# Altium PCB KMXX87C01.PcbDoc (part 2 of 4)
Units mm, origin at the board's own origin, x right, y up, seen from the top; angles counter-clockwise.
Board outline 109.2 x 85.1 mm, 4 copper layers (Top Layer, Mid-Layer 1, Mid-Layer 2, Bottom Layer); 294 components, 222 nets, 951 pads, 352 vias.
Unrouted connection lines stored in the file: 266.
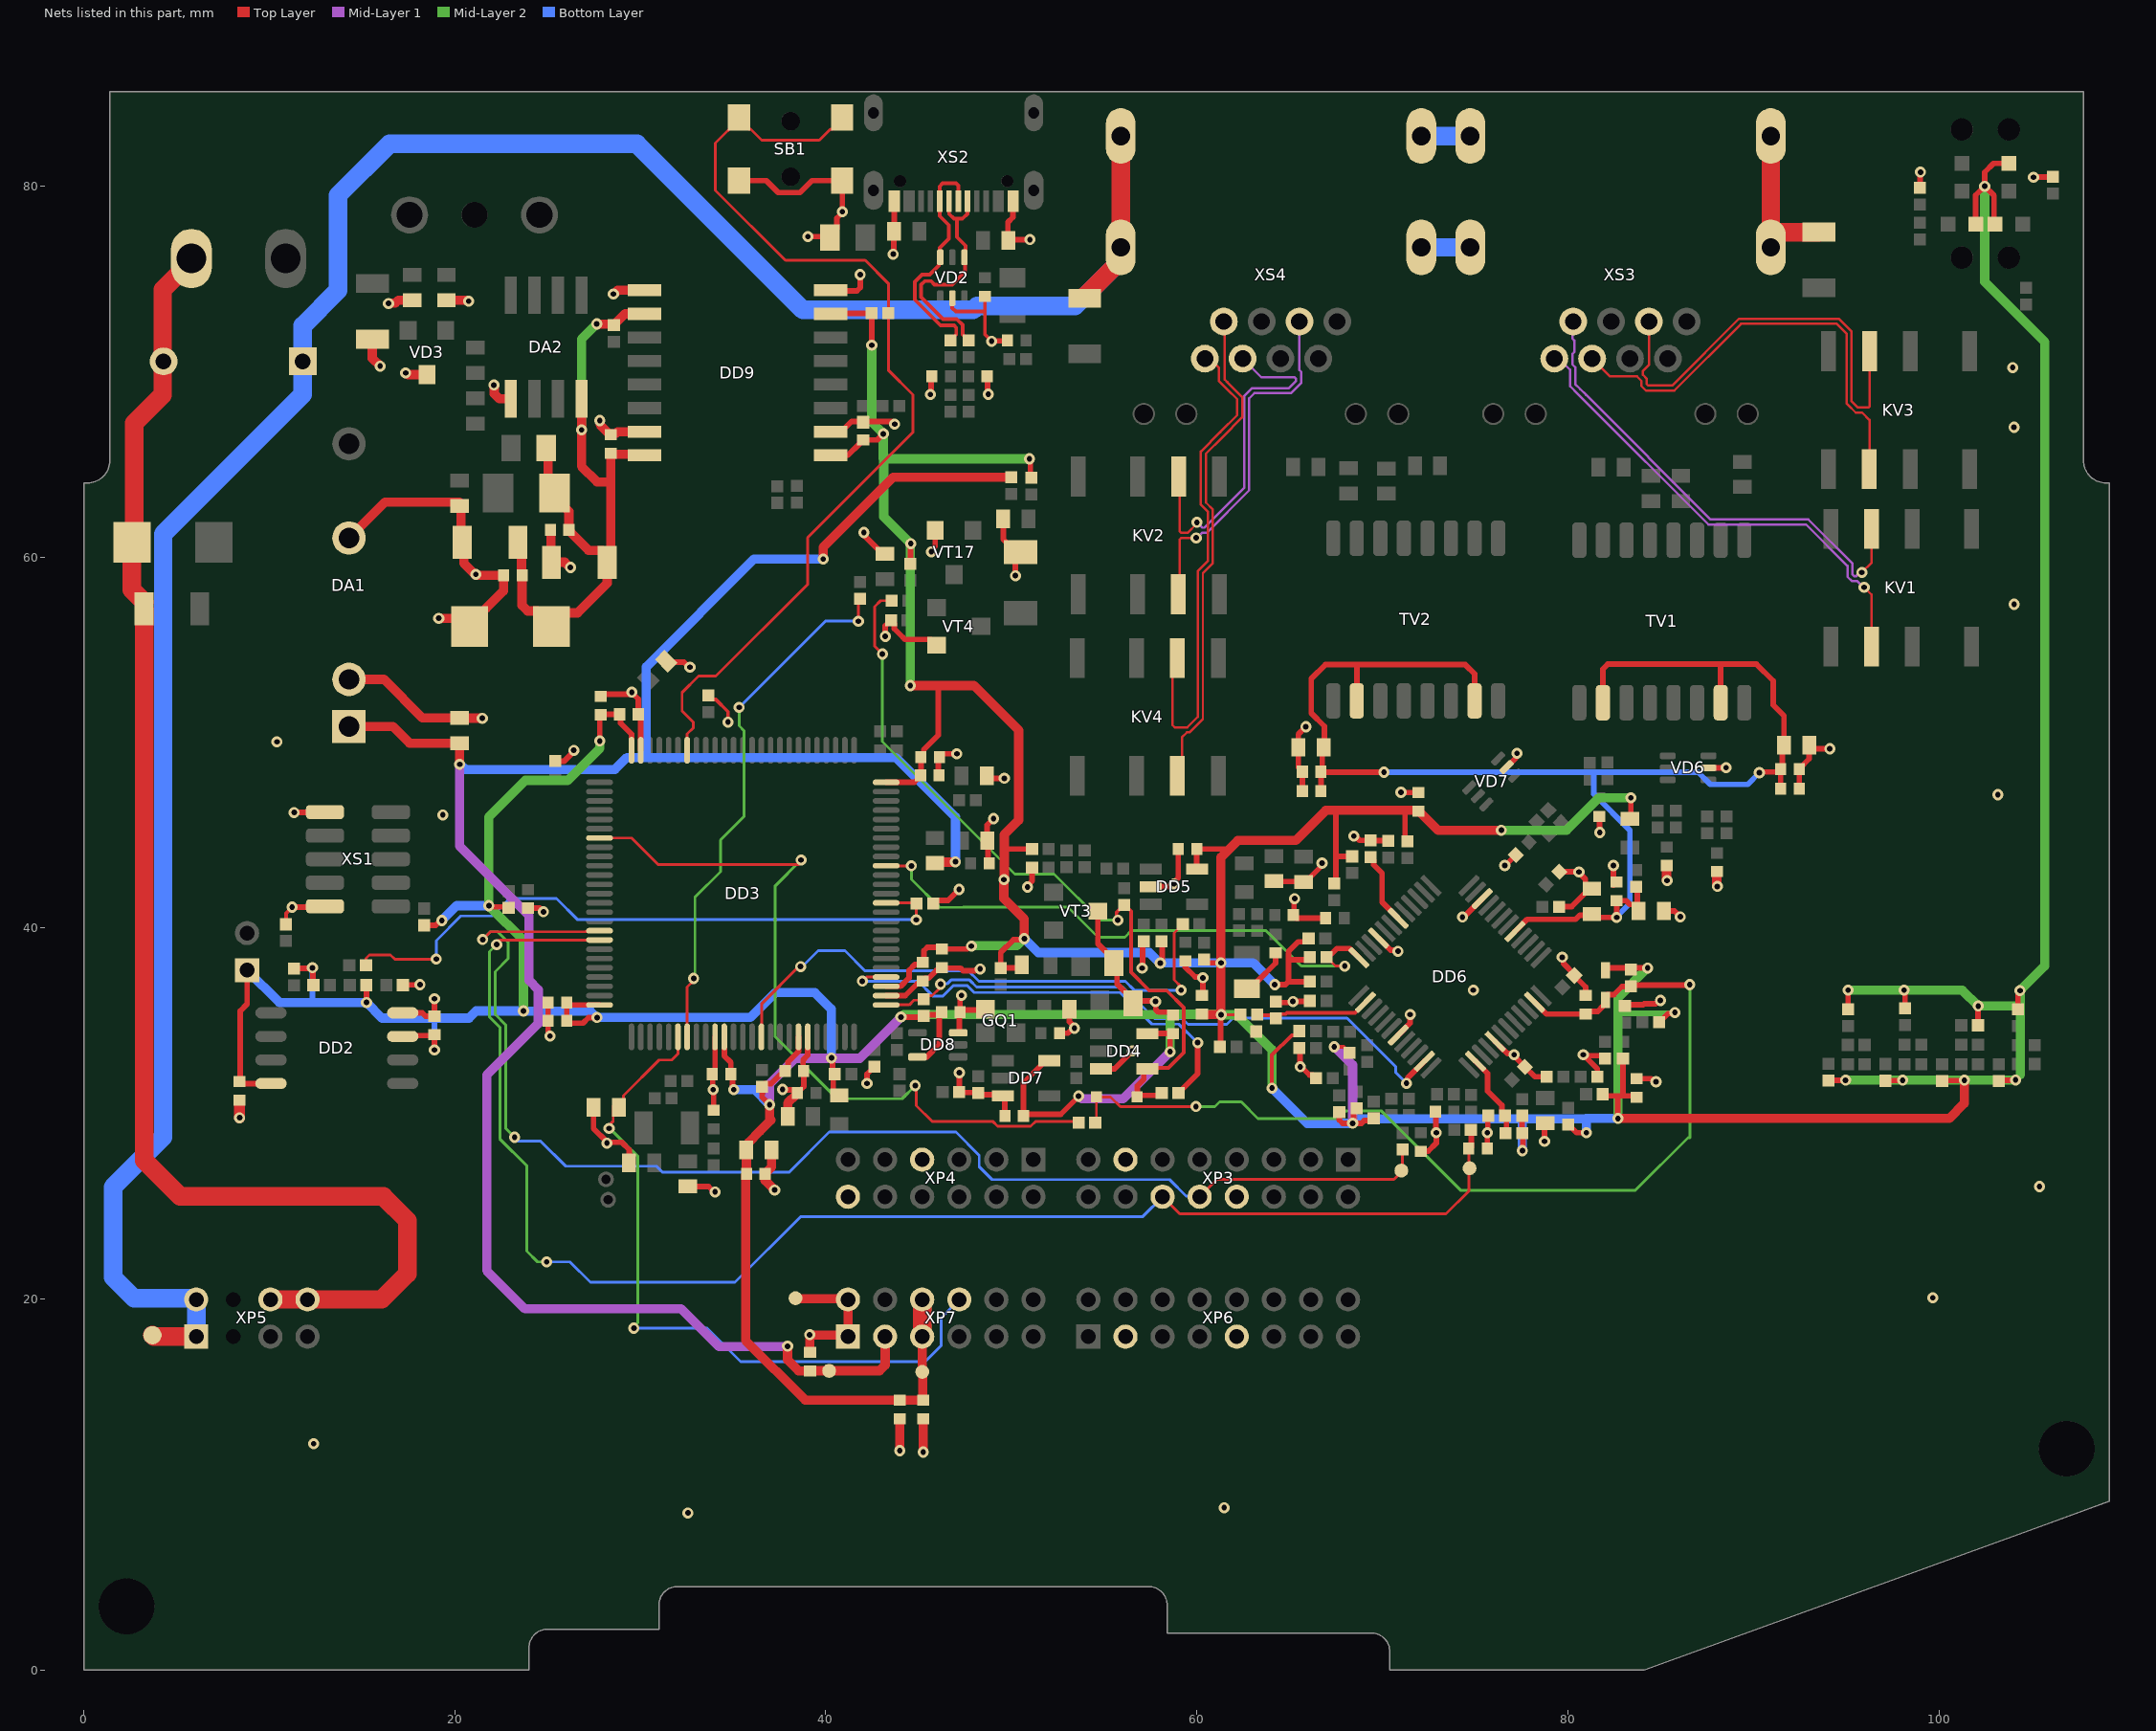
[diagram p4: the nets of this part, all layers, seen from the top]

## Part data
BQ1: library part NX3215SA, "NX3215SA"
BQ2: library part MMTF32, "MMTF32"
C2: library part JY-8, "JY-8"
C3 C4 C5 C6 C10 C12 C13 C14 C15 C16 C18 C19 C21 C24 C25 C26 C28 C29 C30 C31 C32 C33 C34 C35 C36 C37 C39 C40 C42 C44 C45 C47 C48 C50 C51 C53 C54 C55 C56 C57 C58 C59 C60 C72 C73 C74 C75 C76 C120 C122 C124 C125 C126 C144 C145: library part C0402, "C0402"
C7 C8 C9 C11 C17 C20 C22 C23 C27 C43 C46 C61 C102 C146 C169 C170 C171 C172 C173: library part C0603, "C0603"
C38 C49 C62 C63 C67: library part C1206, "C1206"
C41 C52 C150: library part C0805, "C0805"
C64 C65: library part C0603, "C0603", Value2=C0603-50В-100пФ-5%-NPO
DA1: library part F0505S-1W, "F0505S-1W"
DA2: library part ADM485AR, "ADM485AR"
DD2: library part MX25L6433FM2I-08G, "EEPROM Flash Memory, NOR, Serial SPI/QSPI Interface, f=80/133MHz, 64-Mbit, Vcc=2.7V...3.6V, SOIC-8 (200mil). SMT", Value2=MX25L3233FM2I-08G
DD3: library part STM32F207VCT6, "ARM-based 32-bit MCU with 256KB Flash"
DD4: library part SN74LVC1G17DBV, "SN74LVC1G17DBV"
DD5: library part XC6121-24, "Voltage Detector with Watchdog Function and ON/OFF Control"
DD6: library part KSZ8863RLLI, "Integrated 3-Port 10/100 Managed Switch with PHYs"
DD7: library part SN74LVC1G80DBV, "Single Positiive Edge Triggered D-Type Flip-Flop"
DD8: library part SN74LVC1G125DCK, "Buffer / line driver"
DD9: library part ADUM1301, "ADUM1301"
GQ1: library part FXO2520, "SMD Crystal Oscillator 2.5x2.0, 2.0-50.0 MHz, 3.3V", Value2=DSO221SHF, Value3=NZ2520SB
HL1 HL2 HL15 HL16: library part HT19-2132SYGC, "High Brigh Yellow-Green LED"
KV1 KV2 KV3 KV4: library part "Hongfa HFD4/5-S (standard SMT)", "High Frequency / RF Relays 5VDC Non-latching Single coil gullwing", Value2="TE IM03GR Gul wings"
L1 L2 L3 L11: library part L0603, "L0603"
L4 L5 L8: library part L0805, "L0805"
L6: library part L1206, "Inductor, 1206, 1uH, 1200mA, 0.15Ohm", Value2="L1206-1,0мкГн-20% (MURATA, LQM31)"
R1 R9 R14 R16 R18 R23 R25 R26 R40 R98 R99 R100 R101 R106 R107 R325 R329: library part RC03, "RC03"
R2 R3 R4 R5 R6 R7 R8 R10 R11 R12 R15 R17 R19 R20 R21 R22 R24 R27 R28 R29 R30 R31 R32 R33 R34 R35 R36 R37 R38 R39 R41 R42 R43 R44 R45 R46 R47 R49 R50 R51 R52 R53 R54 R55 R56 R57 R58 R59 R60 R61 R62 R63 R64 R65 R66 R67 R68 R69 R70 R71 R72 R73 R74 R75 R76 R77 R78 R79 R80 R81 R82 R83 R84 R85 R86 R87 R88 R89 R90 R91 R92 R93 R94 R95 R96 R97 R102 R103 R104 R105 R108 R109 R110 R111 R112 R113 R114 R115 R169 R200 R201 R202 R233 R234 R268 R269 R270 R271 R318 R319 R320 R321 R322 R326 R327 R357 R358 R378 R380 R381 R383 R400: library part R0402, "R0402"
R48: library part R0402, "R0402", Value2="RC02-1,0кОм 5%"
R116: library part RC06, "Chip Resistor, 1206, Pmax=0.25W, Umax=200V, SIZE=3.2x1.6x0.6mm, SMT"
R167: library part RC03, "RC03", Value2="RC02-0,0 Ом 5%"
R317 R328: library part R0402, "R0402", Value2="RC02-0,0 Ом 5%"
SB1: library part TP-1113, "TP-1113"
T1: library part T17A, "T17A"
T2 T3 T4 T5 T6: library part T07A, "T07A"
TV1 TV2: library part PT61018PEL_TRC1188NLE, "Pulse Transformer 1CT_1CT Lan 10/100 Base TX Transormer Module"
VD1: library part SMBJ6.5, "SM6T27A"
VD2 VD6 VD7: library part TPD4E001DCKR, "4-Channel ESD Protection Array with 1.5pF IO Cap."
VD3: library part SM712, "600W, Asymmetrical TVS Diode Array"
VD4: library part BAS16WS, "BAS16WS", Value2="BAS16HT1G (ON, SOD-323)"
VD5: library part P6KE7,5, "P6KE7,5"
VD8: library part BZV55C, "BZV55C"
VD20: library part BAS716, "Low-Leakage Diode"
VT3: library part BC807-25, "BC807-25"
VT4 VT17: library part BC817-25, "BC817-25"
XP1: library part 2EDGR-5.08-02P, "2EDGR-5.08-02P"
XP2: library part JUMP1X2_2MM, "JUMP1X2_2MM"
XP3 XP6: library part PLD2-16, "PLD2-16", Value2="DS1025-05-2*8 (Connfly)"
XP4 XP7: library part PLD2-12_MULTI, "Pin Header, Straight, Male, POS=12, ROW=2, PITCH=2.0mm, H=6.0mm, I=1.5A, U=125VAC, THT", Value2="DS1025-08-2*6 (Connfly)"
XP5: library part PLD2-08, "Pin Header, Straight, Male, POS=8, ROW=2, PITCH=2.0mm, H=6.0mm, I=1.5A, U=125VAC, THT", Value2="DS1025-05-2*4 (Connfly)"
XS1: library part PBD1.27-10S, "PBD1.27-10S"
XS2: library part USB4105-GF-A-xxx, "USB-C (USB TYPE-C) USB 2.0 Receptacle Connector 24 (16+8 Dummy) Position Surface Mount, Right Angle; Through Hole"
XS3 XS4: library part MJ881B-BX11-HRVL11-X, "RJ45 Offset Low Profile Connector, Latch - Tab UP, Magnetic - none"
XT2: library part 15EDGRC-3.5-03P_MULTI, "Right angle, 3.5 mm pitch, 3 pins", Value2="(1803316) MC 1,5/ 6-G-3,81 - PCB header (Phoenix Contact)"

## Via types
v1: diameter 0.6, hole 0.3, Top Layer to Bottom Layer, tented both sides, 292 vias
v2: diameter 0.6, hole 0.3, Top Layer to Bottom Layer, 60 vias

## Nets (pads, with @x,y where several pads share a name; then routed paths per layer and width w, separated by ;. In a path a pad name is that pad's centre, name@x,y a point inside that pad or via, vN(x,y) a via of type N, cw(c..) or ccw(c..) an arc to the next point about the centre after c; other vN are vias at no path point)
3.3V: C3.1 C5.2 C12.1 C13.1 C14.1 C15.1 C16.1 C18.1 C21.1 C23.1 C24.1 C25.1 C26.1 C28.1 C29.1 C30.1 C32.1 C34.1 C35.1 C37.1 C40.1 C42.1 C144.1 C145.1 DD2.3 DD2.8 DD3.11 DD3.19 DD3.28 DD3.50 DD3.75 DD3.100 DD4.5 DD5.5 DD7.5 DD8.5 DD9.1 DD9.7 HL1.A HL15.A HL16.A L1.2 L3.2 L11.1 R2.2 R11.2 R12.2 R19.2 R21.2 R22.2 R28.1 R29.2 R36.2 R39.2 R41.2 R42.1 R47.1 R49.2 R50.2 R51.2 R54.2 R57.1 R58.1 R60.2 R62.2 R66.1 R67.1 R70.1 R71.2 R80.1 R81.1 R82.1 R83.1 R84.1 R86.1 R103.1 R104.1 R108.1 R110.1 R112.1 R114.1 R167.2 R318.2 R319.2 R320.2 R321.2 R322.2 R326.2 T4.1 VD20.2 XP2.1 XP7.5 XP7.6 | length 494.5
  Top Layer w0.15: v1@61.295,35.344 v1(61.31,35.329) 62.34,35.329 R57.1@62.35,35.338
  Top Layer w0.2: v1(64.05,31.375) 64.05,33.157 65.118,34.225 65.346,34.225 R60.2@65.525,34.404 ; v1(67.404,33.6) 67.913,33.6 R62.2@68.237,33.277
  Top Layer w0.3: C16.1@8.334,31.609 10.08,31.609 DD2.8@10.09,31.619 ; C16.1@8.391,31.716 C16.1@8.4,31.725 8.425,31.75 8.425,35.525 8.8,35.9 XP2.1@8.8,37.729 ; R22.2@11.325,37.807 11.35,37.832 12.3,37.832 v1(12.325,37.857) 12.35,37.832 12.35,36.95 R21.2@12.375,36.925 ; v1(15.236,35.989) R326.2@15.236,36.925 ; DD2.3@17.19,34.159 17.235,34.204 18.854,34.204 C32.1@18.9,34.25 v1(18.9,33.431) ; R19.2@17.2,36.925 17.214,36.939 18.108,36.939 v1(18.123,36.954) ; R2.2@18.35,40.15 18.961,40.15 19.219,40.407 v1(19.3,40.407) ; v1(21.836,41.203) 21.9,41.14 22.698,41.14 R39.2@22.748,41.09 ; C35.1@26.031,35.989 C15.1@26.031,35.001 26.157,34.875 26.911,34.875 27.213,35.177 v1(27.664,35.177) ; C35.1@26.324,35.857 DD3.100@27.8,35.857 ; v1(27.814,50.085) 27.814,51.464 27.875,51.525 C25.1@28.887,51.525 28.932,51.48 28.932,51.05 29.525,50.457 DD3.75@29.525,49.582 ; DD3.11@34.525,34.093 34.525,33.11 34.88,32.754 C34.1@34.88,32.128 ; C34.1@34.884,32.128 34.964,32.049 34.964,31.357 v1(35.032,31.289) ; v1@36.965,30.474 36.565,30.874 R12.2@36.565,31.44 36.74,31.615 37.046,31.615 37.546,32.115 37.661,32.115 37.811,32.265 C28.1@37.811,32.29 ; C28.1@37.961,32.415 37.961,32.786 38.525,33.35 DD3.19@38.525,34.132 ; DD9.1@40.267,65.493 41.19,65.493 41.84,66.142 41.84,66.167 41.99,66.317 42.771,66.317 v1(43.1,66.646) ; DD9.7@40.267,73.113 40.289,73.136 42.447,73.136 R36.2@42.47,73.158 42.472,73.156 42.472,71.428 v1(42.475,71.425) ; v1(40.303,33) 40.368,32.935 40.368,32.232 40.4,32.2 40.4,31.191 L1.2@40.616,30.975 ; DD3.28@43.25,36.857 44.032,36.857 44.494,37.319 44.494,37.724 44.811,38.041 C30.1@45.135,38.041 ; DD3.50@43.25,47.857 44.777,47.857 C37.1@44.985,48.066 ; v1(44.052,35.202) R29.2@45.185,35.202 ; R322.2@44.551,59.645 44.563,59.657 44.563,60.713 v1(44.575,60.725) ; DD8.5@44.938,33.054 44.947,33.063 45.453,33.063 46.12,33.73 46.12,35.288 46.083,35.324 R29.2@45.185,35.324 ; C37.1@45.11,48.244 45.138,48.271 45.138,49.212 C21.1@45.125,49.225 45.275,49.375 45.275,49.613 46.067,50.405 46.067,53.075 ; C30.1@45.225,38.05 45.288,38.113 45.288,38.781 45.463,38.956 46.144,38.956 C14.1@46.162,38.937 ; C14.1@46.25,38.875 47.619,38.875 47.769,39.025 v1(47.85,39.025) ; 49.625,44.357 49.72,44.262 R47.1@51.118,44.262 ; L11.1@50.57,38.018 50.402,37.85 R167.2@49.425,37.85 49.425,38.686 50.107,39.368 50.643,39.368 v1(50.7,39.425) ; v1(50.975,65.3) 51.024,65.251 51.024,64.329 R103.1@51.072,64.281 ; DD7.5@52.134,32.84 51.834,32.84 50.654,31.66 C144.1@50.654,29.862 50.75,29.958 52.666,29.958 53.625,30.917 v2(53.625,30.94) ; DD4.5@57.335,34.313 C40.1@58.56,34.313 ; v1(58.029,38.109) 58.137,38.218 58.137,39.237 R41.2@58.1,39.275 ; v1(58.56,33.336) C40.1@58.56,34.313 ; C40.1@58.712,34.313 C40.1@58.56,34.313 ; C42.1@59.991,44.115 59.991,43.207 DD5.5@60.016,43.182 ; C42.1@60,44.241 C42.1@60,44.266 61.575,44.266 61.657,44.185 ; R28.1@60.4,38.3 60.575,38.125 60.751,38.125 v1@61.295,38.125 ; R58.1@61.25,33.6 61.28,33.63 61.28,35.329 v1@61.295,35.344 ; v1(64.202,36.95) 64.774,36.95 64.935,37.112 ; R70.1@66.029,39.436 65.854,39.261 65.461,39.261 64.935,38.735 64.935,38.3 ; R54.2@66.096,37.112 64.935,37.112 ; R49.2@66.1,38.425 65.975,38.3 64.935,38.3 ; R318.2@67.415,42.405 67.493,42.483 67.493,43.866 ; 67.493,46.35 67.493,43.866 ; R51.2@67.679,30.071 67.679,29.651 67.855,29.475 v1(68.4,29.475) ; R319.2@68.372,43.866 67.493,43.866 ; R50.2@68.537,30.202 68.457,30.122 68.457,29.532 v1(68.4,29.475) ; R321.2@69.537,29.75 69.412,29.625 69.025,29.625 68.875,29.475 v1(68.4,29.475) ; 71.22,46.35 71.22,44.826 71.21,44.817 R320.2@71.356,44.671 ; R67.1@77.537,29.882 R80.1@77.537,28.932 77.576,28.893 77.576,28.027 v1(77.55,28.001) ; R84.1@80.025,29.407 80.467,28.965 v1(81,28.965) ; R81.1@81.885,31.046 81.975,30.956 82.681,30.956 ; VD20.2@82.029,37.725 82.029,37.75 82.129,37.85 v1(84.3,37.85) ; v1(82.704,29.735) 82.681,29.758 82.681,30.956 ; R83.1@82.975,32.975 82.975,30.981 83,30.956 ; L3.2@83.35,45.9 83.4,45.95 v1(83.4,47.024) ; C29.1@83.7,30.885 83.629,30.956 83,30.956 ; R82.1@84.925,34.925 85.393,35.393 85.718,35.393 v1(85.775,35.45) ; R112.1@94.05,31.773 94.064,31.786 94.961,31.786 v1(94.975,31.8) ; R114.1@95.1,35.623 95.109,35.632 v1(95.109,36.653) ; R110.1@97.125,31.767 97.141,31.784 98.034,31.784 v1(98.05,31.8) ; v1(98.126,36.65) 98.175,36.601 R108.1@98.175,35.666 ; R104.1@100.175,31.75 100.2,31.775 101.35,31.775 v1(101.375,31.8) ; HL16.A@101.989,77.956 101.989,79.506 v1(102.475,79.992) ; R86.1@102.112,34.761 102.118,34.767 102.118,35.791 v1(102.125,35.798) ; HL15.A@103.029,77.956 102.975,78.01 102.975,79.492 v1(102.475,79.992) ; R66.1@103.225,31.759 103.252,31.785 104.106,31.785 v1(104.133,31.812) ; HL1.A@103.779,81.226 102.954,81.226 102.475,80.747 v1(102.475,79.992) ; R42.1@104.268,35.619 v1@104.268,36.44 ; 64.935,37.112 64.935,38.3 ; 82.681,30.956 83,30.956
  Top Layer w0.5: v1(36.968,30.478) 36.965,30.474 36.965,29.725 37.04,29.65 36.439,29.05 35.84,28.451 35.84,28.167 C23.1@35.715,28.042 35.715,26.765 35.675,26.725 35.675,17.768 38.893,14.55 C12.1@43.995,14.55 C3.1@45.25,14.55 45.225,14.575 45.225,16.05 T4.1@45.2,16.075 45.198,16.077 45.198,17.974 XP7.5@45.195,17.976 ; v1(44.551,53.075) 46.067,53.075 47.987,53.075 50.4,50.662 50.4,45.814 49.625,45.039 49.625,44.357 v1@49.625,42.612 ; v1(49.6,42.612) 49.6,41.59 50.7,40.49 v1(50.7,39.425) ; C24.1@60.275,35.363 60.292,35.346 61.293,35.346 61.295,35.344 61.295,38.125 61.295,43.823 61.657,44.185 62.199,44.727 65.329,44.727 66.952,46.35 67.493,46.35 71.22,46.35 71.898,46.35 C26.1@71.948,46.3 71.973,46.3 72.998,45.275 v1(76.414,45.275) ; v1(82.704,29.735) 100.567,29.735 101.375,30.543 v1(101.375,31.8)
  Top Layer w1: XP7.5@45.195,17.976 XP7.6@45.195,19.976
  Mid-Layer 1 w0.5: v1(36.968,30.478) 36.965,30.482 36.965,31.59 38.357,32.982 40.285,32.982 v1(40.303,33) ; v1@40.31,32.982 41.833,32.982 v1(44.052,35.202) ; v2(53.625,30.94) 53.652,30.94 53.795,30.797 56.021,30.797 v1(58.56,33.336) ; v1(67.404,33.6) 67.425,33.6 68.4,32.626 v1(68.4,29.475)
  Mid-Layer 2 w0.3: 82.704,35.408 85.733,35.408 v1(85.775,35.45)
  Mid-Layer 2 w0.5: v1(21.836,41.203) 21.836,45.998 23.805,47.967 26.093,47.967 27.814,49.689 v1(27.814,50.085) ; v1@21.9,41.14 23.698,39.341 v1(23.698,35.532) ; v1(42.475,71.425) 42.475,67.295 43.1,66.671 43.1,65.325 43.125,65.3 ; v1(44.052,35.202) 44.193,35.342 58.609,35.342 58.619,35.352 ; v1(44.551,53.075) 44.551,60.701 v1(44.575,60.725) 43.125,62.175 43.125,65.3 ; v1(47.85,39.025) 47.875,39.05 50.298,39.05 50.673,39.425 v1(50.7,39.425) ; v1(50.975,65.3) 43.125,65.3 ; v1(58.56,33.336) 58.56,35.293 58.619,35.352 ; v1@61.183,35.352 58.619,35.352 ; v1(61.31,35.329) 62.161,35.329 64.05,33.44 v1(64.05,31.375) ; v1(76.414,45.275) 79.938,45.275 81.687,47.024 v1(83.4,47.024) ; v1(82.704,29.735) 82.704,35.408 82.704,36.254 v1(84.3,37.85) ; v1(94.975,31.8) v1(98.05,31.8) v1(101.375,31.8) 101.387,31.812 v1@104.134,31.812 ; v1(95.109,36.653) 95.112,36.65 v1(98.126,36.65) 101.273,36.65 v1(102.125,35.798) 104.319,35.798 104.396,35.875 ; v1(102.475,79.992) 102.475,74.839 105.704,71.61 105.704,37.957 v1(104.377,36.63) ; 104.396,32.102 104.396,35.875 ; v1@104.41,36.598 104.396,36.584 104.396,35.875
  Mid-Layer 2 w1: XP7.5@45.195,17.976 XP7.6@45.195,19.976
  Bottom Layer w0.3: v1(12.325,37.857) 12.325,36.055 12.391,35.989 ; v1(18.9,33.431) 18.9,35 19.05,35.15
  Bottom Layer w0.5: XP2.1@8.8,37.729 10.54,35.989 12.391,35.989 v1(15.236,35.989) 16.075,35.15 19.05,35.15 20.769,35.15 21.15,35.532 v1(23.698,35.532) 23.716,35.514 27.307,35.514 27.644,35.177 35.927,35.177 37.275,36.525 39.408,36.525 40.294,35.639 40.294,33.009 v1(40.303,33) ; v1(19.3,40.407) 20.096,41.203 v1(21.836,41.203) ; v1(35.032,31.289) 36.157,31.289 v1(36.968,30.478) ; v1(50.7,39.425) 51.45,38.675 57.436,38.675 58.002,38.109 v1(58.029,38.109) 58.037,38.117 61.292,38.117 v1(61.3,38.125) 63.027,38.125 v1(64.202,36.95) ; v1(64.05,31.375) 65.95,29.475 v1(68.4,29.475) 68.64,29.715 77.565,29.715 ; v1(77.55,28.001) 77.55,29.7 77.565,29.715 ; v1(81,28.965) 81,29.69 80.975,29.715 80.965,29.715 ; v1(82.704,29.735) 80.985,29.735 80.965,29.715 ; 77.565,29.715 80.965,29.715
3.3VDDA: C43.1 C44.1 C57.1 C58.1 C59.1 C60.1 C169.1 C172.1 C173.1 DD6.5 R72.1 TV1.2 TV1.7 TV2.2 TV2.7 | length 82.8
  Top Layer w0.3: C58.1@66.69,47.38 C60.1@66.69,48.43 ; C173.1@66.833,49.747 66.762,49.676 66.762,48.502 C60.1@66.69,48.43 ; C173.1@66.875,49.776 66.875,50.882 66.168,51.589 66.168,53.443 66.925,54.2 68.625,54.2 ; TV2.2@68.624,52.25 68.624,54.199 68.625,54.2 ; v1(70.089,48.404) 66.717,48.404 C60.1@66.69,48.43 ; TV2.7@74.974,52.25 74.974,53.701 74.475,54.2 68.625,54.2 ; DD6.5@77.15,39.818 77.807,40.475 80.425,40.475 80.643,40.693 81.233,40.693 C43.1@81.296,40.756 81.479,40.574 v1(82.631,40.574) 82.631,41.331 C44.1@82.658,41.357 ; TV1.2@81.89,52.15 81.89,53.965 82.15,54.225 88.15,54.225 ; C44.1@82.615,41.481 83.144,41.481 83.349,41.275 83.595,41.275 83.82,41.05 C169.1@83.82,40.925 83.747,40.997 83.747,41.098 83.747,42.153 R72.1@83.675,42.225 ; TV1.7@88.24,52.15 88.24,54.135 88.15,54.225 ; v1@90.297,48.266 90.45,48.419 91.328,48.419 C59.1@91.473,48.564 ; C57.1@91.478,47.514 91.476,47.517 91.476,48.562 C59.1@91.473,48.564 ; 88.15,54.225 90.175,54.225 91.075,53.325 91.075,52.025 91.648,51.452 C172.1@91.648,49.864 91.561,49.777 91.561,48.652 C59.1@91.473,48.564
  Bottom Layer w0.3: v1(70.089,48.404) 81.4,48.404 ; v1(82.631,40.574) 82.631,40.614 83.35,41.333 83.35,45.275 81.4,47.225 81.4,48.404 ; v1(90.325,48.375) 89.7,47.75 87.675,47.75 87.021,48.404 81.4,48.404
5V: C4.2 C9.1 DA1.1 R14.1 R102.1 T3.1 XP7.3 | length 124.7
  Top Layer w0.5: DA1.1@14.291,50.867 16.662,50.867 17.559,49.97 C9.1@20.262,49.97 ; v1@20.263,48.826 C9.1@20.262,49.97 ; v1(37.937,17.458) 37.937,16.721 38.533,16.125 C4.2@39.15,16.125 39.157,16.132 T3.1@40.18,16.132 40.188,16.14 42.902,16.14 43.195,16.433 XP7.3@43.195,17.976 ; v1@39.857,59.876 v1(39.857,59.897) 39.857,60.539 43.618,64.3 R102.1@50,64.3 ; R14.1@45.882,43.502 45.936,43.556 46.967,43.556 v1(46.986,43.575)
  Mid-Layer 1 w0.5: v1(20.263,48.826) 20.263,44.412 24,40.675 24,37.175 24.5,36.675 24.5,34.85 21.725,32.075 21.725,21.537 23.787,19.475 32.201,19.475 34.239,17.437 v1@37.937,17.437
  Bottom Layer w0.5: v1(20.263,48.826) 20.29,48.826 20.566,48.55 28.628,48.55 29.276,49.197 43.779,49.197 46.986,45.991 v1(46.986,43.575) ; 30.322,49.197 30.322,54.082 36.136,59.897 v1(39.857,59.897)
5V_RS: C10.2 C31.2 C38.2 C39.2 C49.2 DA2.8 DD9.10 DD9.16 L5.2 L6.2 R17.2 VD1.2 | length 39.5
  Top Layer w0.5: C49.2@23.282,60.792 23.6,60.474 23.6,59.043 C39.2@23.627,59.017 23.627,57.393 23.92,57.1 24.458,57.1 VD1.2@25.208,56.35 ; L5.2@25.025,66.014 25.025,63.583 26.15,62.458 C31.2@26.15,61.45 ; VD1.2@25.208,56.45 25.755,56.997 26.622,56.997 28.215,58.59 C38.2@28.215,59.031 ; C31.2@26.15,61.475 26.2,61.425 26.2,61.375 27.211,60.364 C38.2@27.957,60.364 ; DA2.8@26.83,68.756 DA2.8@26.83,68.531 v2(26.83,66.86) 26.83,64.895 27.675,64.05 28.375,64.05 ; v2(27.65,72.575) 27.669,72.556 28.528,72.556 R17.2@28.575,72.509 29.179,73.113 DD9.10@30.234,73.113 ; C38.2@28.215,59.925 28.4,60.11 C10.2@28.4,65.6 28.45,65.55 30.176,65.55 DD9.16@30.234,65.493
  Mid-Layer 2 w0.5: v2(26.83,66.86) 26.83,71.755 v2(27.65,72.575)
-IN: C2.2 C67.1 VD5.2 XP1.2 XP5.6 XP5.8 | length 77.2
  Top Layer w1: VD5.2@2.595,60.792 2.595,58.235 C67.1@3.249,57.581 ; VD5.2@2.725,60.792 2.725,67.223 4.25,68.748 4.25,70.55 4.25,74.414 5.206,75.37 5.246,75.37 5.8,75.925 XP1.2@5.8,76.1 ; C67.1@3.249,57.2 3.249,27.476 5.196,25.529 16.146,25.529 17.442,24.233 17.442,21.367 16.051,19.976 XP5.8@12.06,19.976 XP5.6@10.06,19.976
  Mid-Layer 1 w1: XP1.2@5.206,75.37 5.246,75.37 5.8,75.925 XP1.2@5.8,76.1
Auto_Neg_En_P2: DD6.26 R52.2 R57.2 | length 6.3
  Top Layer w0.2: R57.2@63.25,35.338 63.296,35.292 64.088,35.292 64.267,35.113 R52.2@64.267,35.137 64.492,35.362 64.784,35.362 64.856,35.434 68.523,35.434 DD6.26@69.089,35.999
BAT: C27.1 DD3.6 XP7.8 | length 39.2
  Top Layer w0.15: v1(28.318,29.2) 28.317,29.202 28.317,29.363 28.537,29.583 28.537,30.401 C27.1@28.711,30.575 ; C27.1@28.837,30.325 29.083,30.572 29.083,30.962 31.011,32.889 31.695,32.889 32.025,33.219 DD3.6@32.025,34.132
  Mid-Layer 2 w0.15: v1(28.318,29.2) 28.353,29.2 29.874,27.679 29.874,18.735 29.65,18.512 v1(29.65,18.43)
  Bottom Layer w0.15: v1(29.65,18.43) 33.61,18.43 35.415,16.625 45.35,16.625 46.225,17.5 46.225,19.006 XP7.8@47.195,19.976
BOOT1: DD3.37 R24.1 R327.1 | length 35
  Top Layer w0.15: R327.1@15.211,38 15.211,38.373 15.396,38.557 16.531,38.557 16.761,38.327 v1(19.001,38.327) ; DD3.37@43.25,41.357 44.637,41.357 R24.1@44.82,41.175 ; v1(44.875,40.45) 44.875,40.477 44.877,40.48 R24.1@44.877,41.175
  Bottom Layer w0.15: v1(19.001,38.327) 19.001,39.326 20.325,40.65 22.025,40.65 22.964,41.589 25.486,41.589 26.625,40.45 v1(44.875,40.45)
ByPassMode: DD3.41 DD6.24 R49.1 | length 31.2
  Top Layer w0.15: DD3.41@43.25,43.357 43.253,43.355 44.61,43.355 v1(44.612,43.352) ; R49.1@67,38.425 67.475,37.95 v1(67.975,37.95)
  Top Layer w0.3: R49.1@66.875,38.4 67.075,38.6 67.25,38.6 67.552,38.902 68.237,38.902 DD6.24@68.736,38.404
  Mid-Layer 2 w0.15: v1(44.612,43.352) 44.612,42.625 46.124,41.114 47.404,41.114 47.415,41.125 53.06,41.125 54.685,39.5 56.124,39.5 56.499,39.875 63.705,39.875 65.63,37.95 v1(67.975,37.95)
CHASSI: C2.1 C62.2 C63.2 T1.1 XP5.1 XP5.2 XS3.13 XS4.13 | length 145
  Top Layer w1: T1.1@3.7,18.05 3.774,17.976 XP5.1@6.06,17.976 ; C63.2@53.997,74.097 55.901,76 XS4.13@55.901,76.7 XS4.13@55.901,82.7 ; XS3.13@90.94,76.7 XS3.13@90.94,77.238 ; XS3.13@90.94,82.7 XS3.13@90.94,77.238 ; C62.2@93.525,77.521 91.223,77.521 XS3.13@90.94,77.238
  Bottom Layer w1: XP5.1@6.06,17.976 XP5.2@6.06,19.976 6.003,20.033 2.717,20.033 1.575,21.175 1.575,26.043 4.275,28.743 4.275,61.25 11.8,68.775 11.8,72.475 13.7,74.375 13.7,79.5 16.475,82.275 29.82,82.275 38.766,73.329 47.94,73.329 48.15,73.539 53.44,73.539 55.901,76 XS4.13@55.901,76.7 ; XS4.13@72.101,76.7 XS3.13@74.74,76.7 ; XS4.13@72.101,82.7 XS3.13@74.74,82.7
Connect: DD4.4 R31.2 R96.2 R328.1 VD4.2 | length 41.2
  Top Layer w0.15: v1(43.05,54.775) 42.625,55.2 42.625,57.325 42.95,57.65 R96.2@43.541,57.65
  Top Layer w0.2: v1(55.741,40.425) 55.725,40.425 55.669,40.368 55.669,40.844 55.851,41.026 56.299,41.026 56.3,41.025 56.333,41.025 56.45,40.908 56.45,37.617 57.44,36.627 58.377,36.627 59.287,35.717 59.287,33.285 58.466,32.464 57.623,32.464 DD4.4@57.56,32.401
  Top Layer w0.3: DD4.4@57.335,32.263 57.136,32.263 57.136,31.839 56.788,31.491 VD4.2@56.788,30.896 56.868,30.975 57.971,30.975 R31.2@58.11,31.115
  Mid-Layer 2 w0.15: v1(43.05,54.775) 43.05,50.05 50.186,42.914 52.311,42.914 54.8,40.425 v1(55.741,40.425)
Connect_CNTRL: DD3.29 R31.1 | length 24.4
  Top Layer w0.15: v1(41.969,37.135) 41.988,37.154 42,37.154 42.203,37.357 DD3.29@43.25,37.357
  Top Layer w0.3: R31.1@59.01,31.115 60.05,32.154 v1(60.05,33.825)
  Bottom Layer w0.15: v1(41.969,37.135) 44.972,37.135 45.766,36.341 46.316,36.341 46.875,36.9 47.624,36.9 47.999,36.525 55.875,36.525 57.575,34.825 59.026,34.825 60.026,33.825 v1(60.05,33.825)
CPU_OK: DD3.15 R33.2 | length 30.4
  Top Layer w0.15: DD3.15@36.525,34.132 36.554,34.161 36.554,35.932 38.547,37.925 v1(38.64,37.925) ; v1(59.15,36.65) 59.15,36.839 58.776,37.213 58.776,39.74 R33.2@59.241,40.206
  Bottom Layer w0.15: v1(38.64,37.925) 38.735,37.925 39.585,38.775 41.025,38.775 42.092,37.708 47.665,37.708 48.248,37.125 56.15,37.125 56.625,36.65 v1(59.15,36.65)
D1_N: R380.1 VD2.4 XS2.A7 XS2.B7 | length 13
  Top Layer w0.2: XS2.A7@46.64,79.195 46.64,78.513 46.915,78.238 47.065,78.238 ; XS2.B7@47.64,79.195 47.64,78.513 47.365,78.238 47.065,78.238 ; R380.1@47.69,71.688 47.378,72 47.378,72.516 47.055,72.838 46.321,72.838 45.14,74.019 45.14,74.688 45.331,74.879 45.674,74.879 45.865,74.688 46.817,74.688 46.817,74.692 47.5,75.374 47.5,76.132 VD2.4@47.469,76.163 47.525,76.219 47.525,76.791 47.065,77.251 47.065,78.238
D1_P: R381.1 VD2.6 XS2.A6 XS2.B6 | length 13
  Top Layer w0.2: R381.1@46.715,71.688 47.028,72 47.028,72.371 46.91,72.488 46.176,72.488 44.79,73.874 44.79,74.833 45.186,75.229 45.603,75.229 46.094,75.72 46.094,76.088 VD2.6@46.169,76.163 46.14,76.192 46.14,76.665 46.632,77.157 46.632,77.896 46.14,78.388 46.14,79.99 46.3,80.15 47.023,80.15 47.14,80.033 XS2.A6@47.14,79.195
Default: DD3.69 R36.1 SB1.1 | length 54.2
  Top Layer w0.15: DD3.69@32.525,49.582 32.525,50.466 32.85,50.791 32.85,51.1 32.25,51.7 32.25,52.695 33.139,53.584 34.071,53.584 39.016,58.529 39.016,61.051 44.695,66.731 44.695,68.758 43.37,70.084 R36.1@43.37,73.158 43.37,74.755 42.125,76 37.825,76 34.05,79.775 34.05,82.325 SB1.1@35.325,83.6 ; SB1.1@35.325,83.7 SB1.1@35.325,83.6 ; SB1.1@40.875,83.7 40.875,83.6 40.35,83.075 40.25,83.075 39.65,82.475 36.55,82.475 35.95,83.075 35.85,83.075 SB1.1@35.325,83.6
ETH1_RX_N: KV1.3 XS3.2 | length 26.3
  Top Layer w0.127: v2(95.85,59.175) 96.385,59.71 KV1.3@96.385,61.524
  Mid-Layer 1 w0.127: XS3.2@80.29,72.7 80.25,72.66 80.25,71.775 80.35,71.675 80.35,71.05 80.25,70.95 80.25,70.386 80.4,70.236 80.4,69.325 80.662,69.063 80.977,68.748 87.698,62.027 92.966,62.027 95.35,59.643 95.35,59.057 95.434,58.973 95.539,58.973 95.741,59.175 v2(95.85,59.175)
ETH1_RX_P: KV1.6 XS3.1 | length 26.3
  Top Layer w0.127: XS3.1@79.27,70.7 XS3.1@79.43,70.859 ; v2(95.975,58.375) 96.375,57.975 KV1.6@96.375,55.174
  Mid-Layer 1 w0.127: XS3.1@79.27,70.7 79.525,70.7 80.123,70.102 80.123,69.21 80.547,68.786 80.879,68.454 87.583,61.75 92.851,61.75 95.073,59.528 95.073,58.943 95.319,58.696 95.613,58.696 95.934,58.375 v2(95.975,58.375)
ETH1_TX_N: KV3.3 XS3.6 | length 24.3
  Top Layer w0.127: XS3.6@84.37,72.7 84.37,70.357 84.05,70.037 84.05,69.825 84.243,69.632 84.243,69.336 84.329,69.25 85.624,69.25 89.226,72.852 94.615,72.852 95.3,72.167 95.3,68.4 95.637,68.063 96.201,68.063 96.275,68.138 96.275,71.085 KV3.3@96.26,71.1
ETH1_TX_P: KV3.6 XS3.3 | length 24.3
  Top Layer w0.127: XS3.3@81.31,70.7 82.274,69.736 83.733,69.736 83.966,69.503 83.966,69.221 84.214,68.973 85.738,68.973 89.34,72.575 94.5,72.575 95.023,72.052 95.023,68.285 95.104,68.204 95.522,67.786 95.864,67.786 96.26,67.39 96.26,64.76 KV3.6@96.25,64.75
ETH2_RX_N: KV4.3 XS4.2 | length 26.8
  Top Layer w0.127: KV4.3@58.948,48.204 59.201,48.457 59.201,50.285 59.464,50.548 59.605,50.548 60.327,51.27 60.327,59.127 60.867,59.667 60.867,62.567 60.494,62.94 60.494,65.577 61.374,66.457 62.45,67.533 62.45,68.627 61.65,69.427 61.5,69.577 61.5,72.651 XS4.2@61.451,72.7
ETH2_RX_P: KV4.6 XS4.1 | length 26.8
  Top Layer w0.127: KV4.6@58.957,54.554 58.686,54.283 58.686,50.943 58.805,50.825 59.491,50.825 60.05,51.384 60.05,59.242 60.59,59.782 60.59,62.452 60.217,62.825 60.217,65.692 61.259,66.734 62.173,67.648 62.173,68.512 61.65,69.035 61.18,69.505 61.18,70.225 60.705,70.7 XS4.1@60.431,70.7
ETH2_TX_N: KV2.3 XS4.6 | length 19.3
  Top Layer w0.127: KV2.3@59.008,57.995 59.082,58.07 59.082,60.951 59.157,61.025 59.954,61.025 v2(59.963,61.034)
  Mid-Layer 1 w0.127: v2(59.963,61.034) 60.002,61.034 60.274,61.307 60.524,61.307 62.827,63.609 62.827,68.562 63.101,68.836 65.074,68.836 65.63,69.392 65.63,69.981 65.531,70.08 XS4.6@65.531,72.7
ETH2_TX_P: KV2.6 XS4.3 | length 19.3
  Top Layer w0.127: KV2.6@59.017,64.345 59.082,64.28 59.082,61.386 59.159,61.309 59.509,61.309 60.006,61.806 v2(60.006,61.874)
  Mid-Layer 1 w0.127: v2@60.026,61.853 60.035,61.853 60.304,61.584 60.41,61.584 62.55,63.724 62.55,68.677 62.986,69.113 64.959,69.113 65.353,69.507 65.353,69.612 65.279,69.686 63.484,69.686 XS4.3@62.471,70.7
ETH_RELEY_RST: DD3.7 R34.1 | length 28.8
  Top Layer w0.15: DD3.7@32.525,34.132 32.525,36.823 32.875,37.173 v1(32.875,37.287) ; v1(41.753,56.544) 41.753,57.665 R34.1@41.847,57.759
  Mid-Layer 2 w0.15: v1(32.875,37.287) 32.946,37.358 32.946,41.665 34.325,43.044 34.325,44.75 35.6,46.025 35.6,50.625 35.325,50.9 v1(35.325,51.9)
  Bottom Layer w0.15: v1(35.325,51.9) 39.969,56.544 v1(41.753,56.544)
ETH_RST: C50.1 DD6.47 R32.1 R71.1 VD4.1 VD20.1 | length 54.8
  Top Layer w0.15: R32.1@54.588,29.575 VD4.1@54.588,30.896 55.354,30.896 55.879,30.371 59.946,30.371 v2(59.953,30.378)
  Top Layer w0.3: DD6.47@78.211,35.999 78.848,35.363 80.787,35.363 C50.1@80.862,35.437 ; C50.1@80.962,35.363 81.112,35.513 81.617,35.513 81.929,35.825 VD20.1@81.929,36.125 ; VD20.1@82.029,36.125 82.029,36.305 82.129,36.405 82.486,36.405 82.925,36.844 83.319,36.844 83.4,36.925 86.55,36.925 v1(86.575,36.95)
  Mid-Layer 2 w0.15: v2(59.953,30.378) 60.976,30.378 61.223,30.625 62.4,30.625 63.29,29.735 67.61,29.735 68.025,30.15 69.939,30.15 74.239,25.85 83.625,25.85 86.475,28.7 86.575,28.7 v1(86.575,36.95)
ETH_RST_CPU: DD3.82 R32.2 | length 41.4
  Top Layer w0.15: DD3.82@27.8,44.857 29.529,44.857 30.962,43.425 38.552,43.425 38.552,43.431 38.664,43.543 v1(38.664,43.665) ; v1(44.819,31.506) 44.875,31.45 44.875,30.432 45.725,29.583 48.99,29.583 49.261,29.312 51.047,29.312 51.318,29.583 53.553,29.583 R32.2@53.625,29.51
  Mid-Layer 2 w0.15: v1(38.664,43.665) 37.275,42.276 37.275,34.134 40.609,30.8 44.113,30.8 v1(44.819,31.506)
Ext_Ref_Clk_Sel: DD6.18 R53.2 | length 3.9
  Top Layer w0.3: R53.2@69.362,43.827 69.537,43.652 69.537,43.416 69.987,42.966 69.987,41.395 DD6.18@70.857,40.525
Flow_Cntr_En_P1: DD6.38 R76.2 R80.2 | length 4.5
  Top Layer w0.3: DD6.38@75.029,32.817 75.676,32.17 75.676,31.211 76.443,30.444 76.443,30.051 R76.2@76.612,29.882 ; R76.2@76.662,29.882 76.694,29.85 R80.2@76.694,28.965
GND: C3.2 C4.1 C5.1 C6.2 C7.2 C8.2 C9.2 C12.2 C13.2 C14.2 C15.2 C16.2 C17.2 C18.2 C19.2 C20.2 C21.2 C22.2 C23.2 C24.2 C25.2 C26.2 C27.2 C28.2 C29.2 C30.2 C32.2 C33.2 C34.2 C35.2 C36.2 C37.2 C40.2 C41.1 C42.2 C43.2 C44.2 C45.2 C46.2 C47.2 C48.2 C50.2 C51.2 C52.1 C53.2 C54.2 C55.2 C56.2 C57.2 C58.2 C59.2 C60.2 C61.2 C72.1 C73.1 C74.2 C75.1 C76.1 C102.2 C120.2 C122.2 C124.2 C125.2 C126.2 C144.2 C145.2 C146.2 C150.1 C169.2 C170.2 C171.2 C172.2 C173.2 DA1.2 DD2.4 DD3.10 DD3.20 DD3.27 DD3.74 DD4.3 DD5.2 DD6.10 DD6.21 DD6.31 DD6.41 DD7.3 DD8.3 DD9.2 DD9.8 GQ1.2 L4.2 R1.2 R7.1 R9.2 R15.1 R20.2 R23.2 R24.2 R27.2 R30.1 R37.2 R38.1 R44.1 R52.1 R53.1 R55.2 R56.1 R59.2 R61.2 R63.2 R65.2 R68.1 R76.1 R77.1 R78.1 R79.1 R85.2 R97.2 R325.1 R357.1 R378.2 SB1.2 T2.1 VD2.2 VD6.2 VD7.2 VD8.1 VT3.3 VT4.2 VT17.2 XP3.8 XP3.13 XP4.7 XP4.12 XP6.3 XP6.9 XP7.1 XP7.2 XS1.2 XS1.10 XS2.A1_B12 XS2.B1_A12 | length 199.7
  Top Layer w0.2: R20.2@10.9,40.202 10.9,40.799 v1(11.231,41.13) ; R325.1@33.675,52.542 33.9,52.317 34.074,52.317 34.725,51.666 34.725,51.109 v1(34.727,51.107) ; VD2.2@46.819,73.963 46.819,73.432 47.013,73.238 48.58,73.238 ; C73.1@48.58,74.064 48.58,71.996 v1(48.937,71.639)
  Top Layer w0.3: v1(11.231,41.13) 12.956,41.13 XS1.2@13,41.175 ; v1(11.34,46.23) 11.353,46.242 12.988,46.242 XS1.10@13,46.255 ; DD2.4@17.19,35.429 18.246,35.429 18.425,35.25 C32.2@18.9,35.25 v1(18.9,36.189) ; C72.1@24.153,41.019 24.209,41.075 24.575,41.075 v1(24.775,40.875) ; C35.2@25.031,35.989 C15.2@25.031,35.001 25.031,34.358 25.133,34.257 v1(25.133,34.176) ; R7.1@25.407,49 25.417,48.99 25.882,48.99 26.414,49.522 v1(26.414,49.586) ; C27.2@27.477,30.325 27.477,29.193 28.198,28.472 v1(28.198,28.409) ; C18.2@27.875,52.5 27.991,52.616 29.442,52.616 v1(29.542,52.715) ; v1@28.22,28.45 29.002,28.45 29.395,28.057 C7.2@29.395,27.535 ; v1@29.579,52.653 29.887,52.345 C25.2@29.887,51.525 30.025,51.387 DD3.74@30.025,49.582 ; C17.2@31.66,54.33 31.697,54.292 31.8,54.292 31.837,54.33 32.349,54.33 32.619,54.06 v1(32.675,54.06) ; C8.2@32.55,26.07 33.684,26.07 33.979,25.775 v1(34.025,25.775) ; v1@33.878,31.162 33.95,31.09 C33.2@33.95,30.415 ; C34.2@33.88,32.128 33.903,32.106 v1@33.903,31.251 ; v1@33.925,31.229 v1(33.925,31.291) ; C34.2@34.025,32.128 DD3.10@34.025,34.132 ; SB1.2@35.325,80.3 36.789,80.3 37.439,79.65 38.607,79.65 39.257,80.3 SB1.2@40.875,80.3 40.89,80.285 v1(40.89,78.623) 40.89,78.567 40.6,78.277 40.6,77.708 40.171,77.279 v1(39.029,77.279) ; v1(37.667,31.302) 37.685,31.302 37.718,31.269 C19.2@38.325,31.269 ; C19.2@38.475,31.125 38.811,31.461 C28.2@38.811,32.29 38.771,32.33 38.771,32.889 39.025,33.143 DD3.20@39.025,34.132 ; DD9.2@40.267,66.763 40.844,66.763 41.399,67.317 C5.1@42.015,67.317 43.556,67.317 v1(43.708,67.165) ; DD9.8@40.267,74.383 40.299,74.351 41.672,74.351 41.852,74.531 v1(41.852,75.229) ; v1(42.051,61.326) 42.051,61.18 43.056,60.175 C102.2@43.181,60.175 ; v2(42.218,31.625) 42.218,31.668 42.225,31.675 42.225,32.125 R27.2@42.625,32.525 ; v1(43.206,55.728) 43.206,56.291 R97.2@43.512,56.597 43.687,56.422 43.687,56.14 44.152,55.675 44.271,55.556 45.668,55.556 VT4.2@45.976,55.249 ; DD3.27@43.25,36.357 44.279,36.357 44.921,37 45.075,37 C30.2@45.225,37.15 ; v1(43.634,76.331) 43.659,76.356 43.659,77.537 R23.2@43.685,77.563 43.688,77.565 43.688,79.192 XS2.B1_A12@43.69,79.195 ; C30.2@45.25,37.2 45.35,37.3 45.541,37.3 45.966,37.725 46.1,37.725 C14.2@46.25,37.875 ; v1(45.64,68.766) 45.678,68.804 45.678,69.7 C76.1@45.715,69.738 ; v1(45.686,60.29) 45.686,60.371 45.899,60.584 VT17.2@45.899,61.444 ; R24.2@45.882,41.411 45.962,41.491 46.591,41.491 v1(47.183,42.083) ; C37.2@46.11,48.244 46.067,48.288 46.067,49.392 46.075,49.4 v1(47.062,49.4) ; C14.2@46.495,37.845 47.257,37.845 47.4,37.702 48.053,37.702 48.14,37.789 48.315,37.789 v1(48.32,37.795) ; DD8.3@47.138,34.354 47.15,34.354 47.2,34.404 C145.2@47.2,35.267 ; R378.2@47.194,31.157 47.222,31.13 48.189,31.13 R357.1@48.217,31.102 ; R378.2@47.194,31.157 47.194,32.039 v1(47.195,32.207) ; v1(47.309,36.375) 47.309,36.326 47.237,36.254 47.237,35.587 48.57,35.587 GQ1.2@48.6,35.618 ; R357.1@48.217,31.032 48.229,31.021 49.553,31.021 49.654,30.92 C144.2@49.654,29.862 ; C20.2@48.676,48.204 48.805,48.075 v1(49.625,48.075) ; C75.1@48.69,69.738 48.724,69.704 48.724,68.814 v1(48.758,68.78) ; C6.2@48.806,43.499 48.752,43.553 48.752,44.663 R9.2@48.699,44.717 48.699,45.557 v1(49.042,45.9) ; v1(48.937,71.639) 48.953,71.655 49.772,71.655 C74.2@49.789,71.672 ; C61.2@49.564,62.051 49.564,60.961 50.25,60.275 VD8.1@50.5,60.275 50.208,59.983 v1@50.208,59.043 ; XS2.A1_B12@50.09,79.195 50.09,78.32 49.82,78.05 49.82,77.163 49.864,77.119 v1(51.005,77.119) ; v1(50.87,42.215) 50.87,42.293 51.118,42.541 R44.1@51.118,43.267 ; C120.2@52.6,34.328 52.603,34.33 53.05,34.33 53.321,34.602 v1(53.403,34.602) 53.403,34.683 53.13,34.955 C146.2@53.13,35.625 ; VT3.3@54.669,40.911 54.669,39.156 55.529,38.296 C150.1@55.529,38.104 ; DD4.3@54.835,32.413 55.572,32.413 56.524,33.365 v1(56.524,33.375) ; C150.1@55.7,37.964 55.7,36.991 C41.1@56.56,36.13 ; C41.1@56.56,35.746 C41.1@56.918,35.388 ; C41.1@56.56,35.938 56.695,36.073 57.744,36.073 57.788,36.029 57.788,35.595 57.92,35.463 58.562,35.463 C40.2@58.712,35.313 ; v1(57.05,37.84) 57.05,37.878 57.069,37.898 57.069,39.209 R30.1@57.147,39.286 ; DD5.2@57.516,42.232 58.534,42.232 58.686,42.385 v1(58.767,42.385) 58.767,42.466 59,42.698 C42.2@59,44.266 ; C36.2@59.201,38.225 C36.2@59.217,38.208 ; C36.2@59.376,38.225 59.376,37.896 59.909,37.362 60.284,37.362 v1(60.327,37.319) 60.327,36.414 C24.2@60.275,36.363 ; C52.1@62.7,36.724 62.892,36.724 63.25,37.082 63.25,37.114 64.249,38.113 C125.2@64.249,38.66 ; C170.2@64.153,42.528 64.169,42.511 65.73,42.511 C46.2@65.746,42.495 65.871,42.495 66.693,43.316 66.693,43.443 v1(66.75,43.5) ; R52.1@64.326,35.985 65.125,35.985 v1(65.182,36.042) ; C51.2@65.202,40.693 65.239,40.73 65.239,41.55 v1(65.275,41.587) ; v1@65.218,36.042 66.065,36.042 R55.2@66.096,36.073 ; C51.2@65.352,40.537 C45.2@66.943,40.537 ; R61.2@65.525,33.525 65.562,33.487 65.562,32.588 66.075,32.075 66.25,32.075 R63.2@66.425,31.9 ; C58.2@65.69,47.38 C60.2@65.69,48.43 65.69,48.455 65.473,48.673 C173.2@65.473,49.747 65.473,50.449 v1(65.877,50.853) ; v1(68.465,44.956) 68.547,44.956 68.775,44.727 R53.1@69.362,44.727 69.376,44.714 70.311,44.714 R56.1@70.325,44.7 ; DD6.21@69.796,39.464 70.453,38.807 70.786,38.807 v1(70.843,38.75) ; DD6.31@70.857,34.232 71.5,34.875 v1(71.5,35.338) ; v1(71.004,47.322) 71.015,47.311 71.937,47.311 C26.2@71.948,47.3 ; C122.2@72.081,27.971 72.472,27.971 72.906,28.405 v1(72.906,28.965) 72.884,28.988 72.884,30.085 C124.2@72.862,30.107 ; v1(74.322,40.596) 74.392,40.596 DD6.10@75.382,41.586 ; C126.2@75.705,28.001 75.662,28.044 C126.2@75.662,28.107 v1(75.662,28.965) 75.662,28.982 75.687,29.007 75.687,29.857 R76.1@75.712,29.882 ; DD6.41@76.089,33.878 76.509,33.458 76.526,33.458 76.75,33.234 77.046,33.234 v1(77.104,33.177) 77.104,33.106 C47.2@77.69,32.52 78.228,31.982 R85.2@78.864,31.982 ; v1(76.601,43.375) 76.627,43.375 77.19,43.938 C53.2@77.197,43.938 ; VD7.2@76.703,48.678 77.206,49.181 77.206,49.366 v1(77.263,49.423) ; v1(78.74,28.506) 78.74,29.438 C171.2@78.78,29.477 ; R65.2@79.525,41.15 80.205,41.15 C43.2@81.171,42.117 ; C48.2@79.536,43.045 79.553,43.027 79.766,43.027 79.769,43.03 80.598,43.03 v1(80.601,43.027) ; v1(79.7,38.425) 79.757,38.368 79.757,38.093 80.343,37.507 R68.1@80.343,37.443 80.962,36.825 C50.2@80.962,36.363 ; v1@80.564,43.027 80.946,42.644 80.946,42.342 C43.2@81.171,42.117 ; v1(80.829,33.177) v1@80.886,33.119 ; C43.2@81.296,42.117 C43.2@81.171,42.117 ; R77.1@81.435,32.088 81.435,32.14 R77.1@81.593,31.982 81.593,32.413 v1@80.886,33.119 ; C54.2@81.689,46.024 81.707,46.007 81.707,45.169 v1(81.725,45.151) ; R79.1@82,32.975 81.856,33.119 v1@80.886,33.119 ; C44.2@82.46,42.3 v1(82.46,43.372) ; R78.1@83.075,35.8 83.137,35.863 84.063,35.863 84.125,35.925 84.734,35.925 84.909,36.1 v1(84.99,36.1) ; C29.2@83.7,31.885 84.496,31.885 84.67,31.712 v1(84.751,31.712) ; C169.2@85.18,40.925 85.742,40.925 v1(86.061,40.606) ; VD6.2@87.585,48.636 88.513,48.636 v1(88.529,48.652) ; C57.2@92.478,47.514 92.476,47.517 92.476,48.562 C59.2@92.473,48.564 92.473,48.589 93.008,49.124 C172.2@93.008,49.864 93.206,49.666 v1(94.122,49.666) ; R37.2@98.983,79.908 98.998,79.923 98.998,80.74 v2(99.012,80.755) ; v2(105.104,80.476) 105.119,80.491 106.135,80.491 R38.1@106.15,80.507
  Top Layer w0.5: DA1.2@14.291,53.407 16.182,53.407 18.258,51.33 C9.2@20.262,51.33 20.272,51.32 21.469,51.32 v1(21.479,51.31) ; C23.2@37.075,28.042 37.075,27.125 36.725,26.775 C13.2@36.725,26.75 36.725,26.395 v1(37.241,25.879) ; C22.2@37.945,29.85 37.945,30.57 38.4,31.025 38.425,31.025 38.475,31.075 C19.2@38.475,31.1 ; T2.1@38.365,20.05 38.402,20.013 41.158,20.013 XP7.2@41.195,19.976 41.195,18.136 41.115,18.056 39.149,18.056 v1@39.14,18.065 ; v1(39.129,18.075) v1@39.14,18.065 ; C4.1@39.15,17.125 39.14,17.135 v1@39.14,18.065 ; v1(43.99,11.825) 43.993,11.827 43.993,13.548 C12.2@43.995,13.55 ; v1(45.25,11.75) C3.2@45.25,13.55 ; C55.2@85.331,43.372 85.321,43.362 85.321,42.595 v1(85.353,42.563) ; C56.2@88.035,43.046 88.035,43.005 88.026,42.996 88.026,42.307 88.06,42.273 v1(88.06,42.246)
  Top Layer w0.6: v1(8.4,29.775) C16.2@8.4,30.725
  other v1: 65.578,32.519 57.775,36.042 74.905,36.653 19.35,46.1 50.223,58.998
  other v2: 32.566,8.468 61.47,8.755 12.391,12.2 99.672,20.068 105.425,26.068 103.183,47.194 10.411,50.045 104.059,57.454 104.05,67 103.981,70.221
GND_RS: C10.1 C11.2 C31.1 C38.1 C39.1 C49.1 C64.1 C65.1 DA1.5 DA2.5 DD9.9 DD9.15 R116.1 VD1.1 VD3.3 | length 32.2
  Top Layer w0.5: DA1.5@14.291,61.027 16.226,62.962 C11.2@20.262,62.962 ; R116.1@15.55,71.75 15.55,70.719 v2(15.975,70.294) ; v2(16.425,73.675) 16.444,73.694 16.795,73.694 16.948,73.847 C64.1@17.698,73.847 ; v2(17.35,69.925) 17.377,69.925 17.468,69.834 VD3.3@18.498,69.834 ; v1(19.133,56.704) 20.344,56.704 VD1.1@20.798,56.25 ; C65.1@19.548,73.847 20.676,73.847 20.723,73.8 v2(20.75,73.8) ; C11.2@20.262,62.762 20.331,62.693 20.331,60.868 C49.1@20.399,60.8 20.489,60.71 20.489,59.661 21.133,59.017 C39.1@22.627,59.017 22.627,58.179 21.698,57.25 VD1.1@20.798,56.35 ; VD1.1@20.798,56.45 VD1.1@20.798,56.55 ; v2(22.105,69.275) 22.124,69.256 22.124,68.808 22.401,68.531 DA2.5@23.02,68.531 ; C31.1@25.15,61.475 25.182,61.443 25.182,59.757 C38.1@25.214,59.725 25.925,59.725 26.204,59.445 v1(26.232,59.445) ; v1(27.814,67.361) 27.834,67.342 27.834,67.141 28.375,66.6 C10.1@28.4,66.6 28.45,66.65 28.655,66.65 28.768,66.763 DD9.15@30.234,66.763 ; v1(28.546,74.182) 28.573,74.182 28.774,74.383 DD9.9@30.234,74.383
  other v1: 21.133,59.07
I2C_SCL: DD3.92 R268.2 T6.1 XP3.10 | length 72.6
  Top Layer w0.15: v1(21.501,39.382) 21.919,39.8 27.061,39.8 27.09,39.829 27.771,39.829 DD3.92@27.8,39.857 ; XP3.10@60.153,25.515 61.092,26.454 70.628,26.454 71.091,26.918 R268.2@71.091,28.056
  Mid-Layer 2 w0.15: v1(21.501,39.382) 21.919,39.8 22.31,39.8 22.875,39.235 22.875,38.352 22.173,37.65 22.173,35.35 22.75,34.773 22.75,29.197 v1(23.222,28.725)
  Bottom Layer w0.15: v1(23.222,28.725) 23.439,28.508 24.632,28.508 25.98,27.16 30.87,27.16 31.18,26.85 38.035,26.85 40.185,29 47.019,29 48.27,27.749 48.27,27.132 48.812,26.59 48.962,26.44 58.536,26.44 59.428,25.549 60.12,25.549 XP3.10@60.153,25.515
I2C_SDA: C126.1 DD3.93 R269.2 T5.1 XP3.12 | length 80.8
  Top Layer w0.15: v1(22.254,39.113) 22.254,39.212 22.4,39.357 DD3.93@27.8,39.357 ; XP3.12@58.153,25.515 59.078,24.59 73.427,24.59 74.662,25.825 C126.1@74.662,28.107
  Top Layer w0.3: R269.2@74.772,29.132 74.792,29.112 74.792,28.203 C126.1@74.812,28.182
  Mid-Layer 2 w0.15: v1(22.254,39.113) 21.873,38.732 21.873,35.209 22.425,34.658 22.425,28.636 23.875,27.186 23.875,22.585 24.455,22.005 v1(24.95,22.005)
  Bottom Layer w0.15: v1(24.95,22.005) 26.206,22.005 27.311,20.9 35.103,20.9 38.653,24.45 57.088,24.45 XP3.12@58.153,25.515
INTRN: DD3.26 DD6.35 R29.1 | length 33.1
  Top Layer w0.15: DD3.26@43.25,35.857 44.497,35.857 44.752,36.112 45.072,36.112 45.311,36.35 45.732,36.35 46.102,36.72 46.102,36.889 v1(46.188,36.975)
  Top Layer w0.3: v1(71.298,31.632) 71.356,31.69 71.356,31.902 DD6.35@72.271,32.817
  Bottom Layer w0.15: v1(46.188,36.975) 46.225,37.012 46.563,37.012 46.751,37.2 47.749,37.2 48.124,36.825 56.025,36.825 57.725,35.125 59.2,35.125 59.521,34.804 61.611,34.804 61.958,35.15 68.1,35.15 70.731,32.519 70.731,32.199 v1(71.298,31.632)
